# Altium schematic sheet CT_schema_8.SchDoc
size 278 x 170 mm
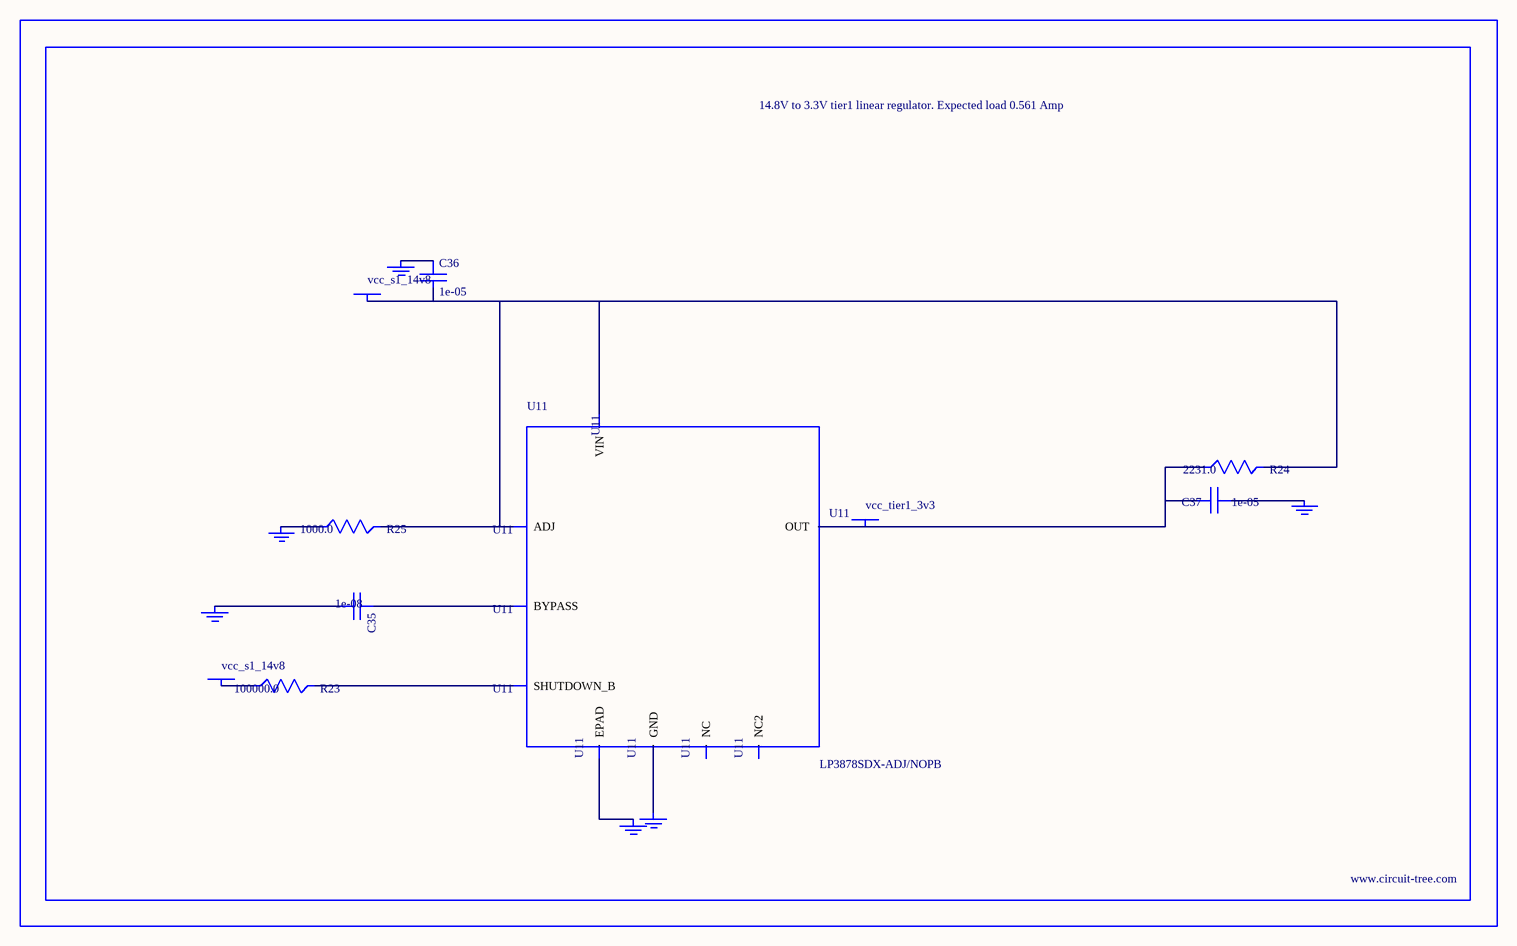
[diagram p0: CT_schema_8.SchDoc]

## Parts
BORDER7  (no value)
C35  1e-08  [C0402]
C36  1e-05  [C1210]
C37  1e-05  [C1210]
GND_INSTANCE_7_0  (no value)
GND_INSTANCE_7_1  (no value)
GND_INSTANCE_7_2  (no value)
GND_INSTANCE_7_3  (no value)
GND_INSTANCE_7_4  (no value)
GND_INSTANCE_7_5  (no value)
POWER_INSTANCE_7_0  vcc_s1_14v8
POWER_INSTANCE_7_1  vcc_s1_14v8
POWER_INSTANCE_7_2  vcc_tier1_3v3
R23  100000.0  [R0603]
R24  2231.0  [R0603]
R25  1000.0  [R0603]
U11  LP3878SDX-ADJ/NOPB  [WSON-8]

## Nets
NetC35_1: C35.1 U11.1(BYPASS)
NetC35_2: C35.2 GND_INSTANCE_7_0.0(GND)
NetC36_1: C36.1 GND_INSTANCE_7_1.0(GND)
NetC36_2: C36.2 POWER_INSTANCE_7_0.0(PWR) R24.2 R25.2 U11.4(VIN) U11.6(ADJ)
NetC37_1: C37.1 GND_INSTANCE_7_2.0(GND)
NetC37_2: C37.2 POWER_INSTANCE_7_2.0(PWR) R24.1 U11.5(OUT)
NetGND_INSTANCE_7_3_0: GND_INSTANCE_7_3.0(GND) R25.1
NetGND_INSTANCE_7_4_0: GND_INSTANCE_7_4.0(GND) U11.PAD(EPAD)
NetGND_INSTANCE_7_5_0: GND_INSTANCE_7_5.0(GND) U11.3(GND)
NetPOWER_INSTANCE_7_1_0: POWER_INSTANCE_7_1.0(PWR) R23.1
NetR23_2: R23.2 U11.8(SHUTDOWN_B)

Not connected (* = marked no-connect by the designer): U11 2(NC) 7(NC2)

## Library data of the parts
BORDER7 = BORDER_PAGE7
C35 = C0402C103K3RAC
C36 = C1210C106K5PACTU
C37 = GRM32DR61E106MA12L
GND_INSTANCE_7_0-GND_INSTANCE_7_5 = GND
POWER_INSTANCE_7_0-POWER_INSTANCE_7_2 = PWR
R23 = RC0603JR-07100KL
R24 = R24
R25 = RC0603JR-071KL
